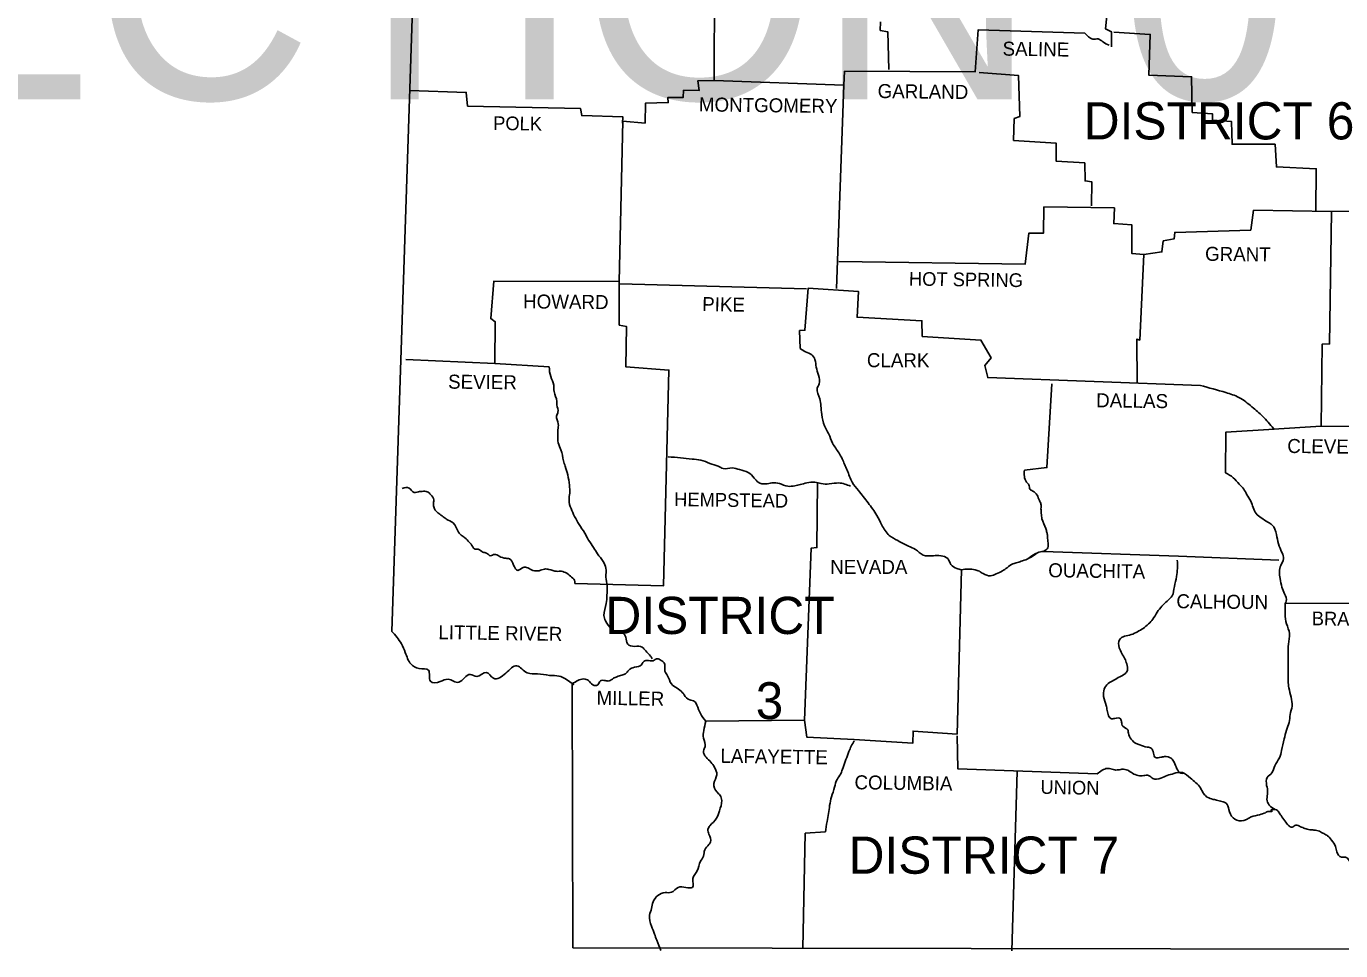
# Model space of a CAD drawing. Extents: x 166 to 3995, y -61 to 2074.
# Drawn here: x 2605.5 to 2999.8, y 1432.6 to 1709.8 of the extents above; entities that cross this region are included whole.
import ezdxf

# ---------------------------------------------------------------- set-up
doc = ezdxf.new("R2010")
doc.units = 0
for name, color, linetype in [('1', 7, 'Continuous'), ('2', 7, 'Continuous'), ('3', 7, 'Continuous')]:
    doc.layers.add(name, color=color, linetype=linetype)

msp = doc.modelspace()

# ---------------------------------------------------------------- linework, layer by layer
at = {"layer": '1'}
for points in [[(2703.71, 1956.42), (2723.96, 1793.81), (2715.15, 1528.37)], [(2812.02, 1750.86), (2811.82, 1693.62), (2806.93, 1693.52), (2807.32, 1690.59), (2802.62, 1690.68), (2802.53, 1688.53), (2797.93, 1688.53), (2798.03, 1686.97), (2791.18, 1686.77), (2791.08, 1680.8), (2784.43, 1681.39), (2783.35, 1633.25), (2745.68, 1633.35), (2744.8, 1622.19), (2746.17, 1621.22), (2746.07, 1608.69), (2719.36, 1609.87)], [(2961.91, 1722.77), (2954.86, 1723.56), (2955.16, 1720.92), (2942.34, 1720.43), (2941.95, 1716.61), (2929.91, 1715.93), (2929.23, 1709.08), (2930.99, 1708.2), (2930.99, 1703.7)], [(2922.97, 1707.81), (2890.97, 1708.78), (2890.09, 1696.16), (2850.96, 1696.36), (2850.76, 1692.15)], [(2861.72, 1711.23), (2861.62, 1708.59), (2863.87, 1708.2), (2864.26, 1696.85)], [(2931.68, 1708.1), (2942.63, 1707.41), (2942.24, 1695.18), (2955.06, 1694.69), (2955.26, 1684.03), (2961.32, 1683.54), (2961.32, 1681.68), (2967, 1681.29), (2967.19, 1674.44), (2980.11, 1674.44), (2980.5, 1667.69), (2992.44, 1667.1), (2992.34, 1654.38)], [(2891.27, 1695.97), (2903.11, 1695.09), (2903.5, 1682.76), (2901.83, 1682.17), (2901.64, 1675.62), (2914.46, 1674.74), (2914.46, 1669.35), (2922.97, 1668.86), (2923.07, 1663.48), (2925.12, 1663.19), (2925.02, 1655.95)], [(2850.76, 1692.15), (2811.82, 1693.62)], [(2850.76, 1692.15), (2848.51, 1631.2)], [(2720.54, 1690.59), (2737.46, 1690), (2737.85, 1685.89), (2771.71, 1685.2), (2772.1, 1683.05), (2784.43, 1682.66), (2784.33, 1680.8)], [(3109.06, 1665.64), (3072.08, 1666.61), (3071.88, 1654.58), (2997.03, 1654.29)], [(2849.2, 1639.32), (2905.16, 1638.53), (2906.24, 1647.83), (2910.64, 1647.83), (2910.74, 1655.66), (2931.87, 1655.36), (2931.68, 1650.67), (2937.16, 1650.27), (2937.16, 1641.66), (2940.68, 1641.37)], [(2940.68, 1641.37), (2946.16, 1642.15), (2946.55, 1645.48), (2949.78, 1646.07), (2949.97, 1648.02), (2972.77, 1648.71), (2973.65, 1654.68), (2997.03, 1654.29)], [(2997.03, 1654.09), (2996.45, 1614.56), (2994.2, 1614.47), (2993.9, 1589.91)], [(2940.68, 1641.37), (2939.5, 1615.74), (2938.62, 1616.03), (2938.72, 1602.72)], [(2783.35, 1633.25), (2783.35, 1620.24), (2785.5, 1619.85), (2785.31, 1607.71), (2798.22, 1606.74), (2796.66, 1542.06), (2770.04, 1542.75)], [(2783.55, 1632.57), (2839.51, 1631.1)], [(2837.65, 1613.19), (2837.46, 1618.57), (2839.02, 1618.67), (2840, 1631.29), (2855.07, 1630.32), (2854.68, 1622.59), (2874.15, 1621.51), (2874.24, 1616.81), (2891.85, 1615.74), (2894.89, 1610.45), (2893.03, 1608.11), (2893.91, 1604.49), (2957.7, 1602.14)], [(2746.07, 1608.69), (2762.31, 1607.71)], [(2913.09, 1602.63), (2911.62, 1577.48), (2904.87, 1576.7)], [(2993.9, 1589.91), (2979.62, 1589.03)], [(2993.9, 1589.91), (3028.54, 1589.71)], [(2979.81, 1589.03), (2965.33, 1588.15), (2965.24, 1575.92)], [(2842.84, 1572.98), (2842.64, 1553.51), (2840.88, 1553.31), (2838.92, 1501.75)], [(2910.64, 1552.34), (2951.15, 1550.87), (2981.18, 1549.69)], [(2885.98, 1546.86), (2884.71, 1497.55), (2871.5, 1498.43), (2871.41, 1494.81), (2853.79, 1495.88)], [(2983.14, 1536.68), (3027.36, 1536.78)], [(2769.26, 1512.61), (2769.46, 1433.46), (3128.04, 1432.87)], [(2853.79, 1495.88), (2839.61, 1496.67), (2838.92, 1501.75), (2809.28, 1501.46)], [(2926.69, 1485.61), (2884.91, 1487.17), (2884.71, 1497.06)], [(2902.72, 1486.29), (2901.15, 1432.58)], [(2845.18, 1468.19), (2839.12, 1467.8), (2838.43, 1433.36)]]:
    msp.add_lwpolyline(points, dxfattribs=at)
for points in [[(2930.31, 1704.19), (2928.45, 1705.16), (2926.98, 1706.04), (2925.41, 1705.95), (2924.14, 1706.73), (2922.97, 1707.81)], [(2837.65, 1613.19), (2839.22, 1612.21), (2841.08, 1611.33), (2842.05, 1609.87), (2842.45, 1607.62), (2843.13, 1605.17), (2843.33, 1602.63), (2842.74, 1601.26), (2843.52, 1598.13), (2843.82, 1595.97), (2844.11, 1593.43), (2844.89, 1590.01), (2846.16, 1587.66), (2847.34, 1584.82), (2849.29, 1581.79), (2850.96, 1578.46), (2851.74, 1576.7), (2853.21, 1573.08), (2855.07, 1570.63), (2858, 1566.91), (2860.64, 1563.1), (2862.11, 1560.26), (2864.36, 1557.13), (2866.91, 1555.57), (2870.13, 1553.9), (2872.19, 1552.92), (2874.54, 1551.26), (2877.57, 1551.06), (2879.82, 1551.06), (2881.88, 1550.18), (2882.85, 1548.42), (2884.61, 1547.25), (2885.98, 1546.86)], [(2762.31, 1607.71), (2762.8, 1604.78), (2763.68, 1602.24), (2763.78, 1600.28), (2764.66, 1597.34), (2764.66, 1596.27), (2764.96, 1594.11), (2764.56, 1592.94), (2765.05, 1590.59), (2764.96, 1588.83), (2764.96, 1587.36), (2765.05, 1584.92), (2765.84, 1582.76), (2766.62, 1579.54), (2767.11, 1577.87), (2767.89, 1575.33), (2768.38, 1572.2), (2768.48, 1569.85), (2768.28, 1567.7), (2768.87, 1565.25), (2769.95, 1562.81), (2771.32, 1560.46), (2772.98, 1557.82), (2774.15, 1555.76), (2775.62, 1553.51), (2776.79, 1551.65), (2778.56, 1549.3), (2779.34, 1547.35), (2779.34, 1544.61), (2779.73, 1542.06), (2779.63, 1539.23), (2779.44, 1536.68), (2778.75, 1533.16), (2779.24, 1531.5), (2781.1, 1529.05), (2782.27, 1528.37), (2784.33, 1527.97), (2785.31, 1526.6), (2785.89, 1524.55), (2787.95, 1523.86), (2790.2, 1523.67), (2791.27, 1522.49), (2792.74, 1520.93), (2793.23, 1520.15)], [(2957.7, 1602.14), (2965.33, 1599.98), (2969.25, 1598.52), (2973.16, 1595.68), (2976.39, 1592.84), (2979.62, 1589.22)], [(2798.03, 1580.71), (2801.74, 1580.42), (2805.17, 1580.03), (2807.81, 1579.73), (2810.55, 1578.75), (2813, 1577.87), (2814.56, 1577.19), (2817.2, 1577.38), (2819.45, 1576.89), (2822, 1576.01), (2823.86, 1574.35), (2825.03, 1573.08), (2827.28, 1572.59), (2829.14, 1572.88), (2831.39, 1572.69), (2833.93, 1571.9), (2835.99, 1572), (2837.65, 1572.39), (2839.61, 1572.88), (2842.05, 1573.08), (2843.91, 1572.69), (2846.36, 1572.59), (2849.2, 1572.88), (2852.72, 1571.9)], [(2904.87, 1576.7), (2904.87, 1574.84), (2905.55, 1573.08), (2906.24, 1572.3), (2906.53, 1571.02), (2907.41, 1570.44), (2908.68, 1569.26), (2909.37, 1567.6), (2909.86, 1566.52), (2909.86, 1565.15), (2909.96, 1563.78), (2910.15, 1562.12), (2911.33, 1559.19), (2911.62, 1558.01), (2911.81, 1557.03), (2911.91, 1555.37), (2911.91, 1553.41), (2910.64, 1552.34)], [(2965.24, 1575.92), (2967.49, 1574.45), (2969.34, 1572.49), (2970.71, 1571.02), (2971.59, 1569.36), (2972.77, 1567.4), (2974.43, 1563.69), (2975.9, 1562.41), (2977.95, 1561.14), (2979.23, 1560.26), (2980.5, 1557.42), (2981.09, 1554.59), (2982.16, 1552.04), (2982.65, 1550.09), (2981.77, 1548.13), (2981.57, 1544.22), (2982.16, 1541.57), (2982.94, 1539.62), (2983.43, 1537.37), (2983.14, 1536.68)], [(2718.19, 1571.22), (2720.34, 1571.32), (2721.81, 1570.05), (2722.69, 1570.14), (2724.25, 1570.34), (2725.72, 1570.24), (2726.8, 1569.36), (2727.68, 1567.8), (2727.58, 1566.33), (2727.68, 1565.74), (2728.36, 1564.47), (2729.54, 1563.49), (2730.81, 1562.51), (2731.98, 1561.73), (2733.94, 1560.46), (2734.14, 1560.07), (2734.92, 1558.5), (2735.9, 1557.23), (2737.07, 1556.45), (2738.34, 1555.08), (2738.93, 1554.49), (2739.91, 1553.12), (2740.98, 1553.02), (2742.45, 1552.14), (2743.53, 1551.85), (2744.7, 1551.06), (2745.88, 1551.46), (2747.34, 1550.87), (2749.3, 1550.28), (2750.38, 1550.09), (2751.65, 1548.23), (2752.92, 1546.66), (2754.49, 1547.54), (2757.42, 1546.66), (2759.28, 1546.56), (2760.94, 1547.05), (2762.22, 1546.96), (2764.56, 1546.37), (2766.03, 1546.37), (2767.6, 1545.78), (2769.06, 1544.61), (2770.04, 1543.34), (2770.04, 1542.75)], [(2908.78, 1551.95), (2906.24, 1550.28), (2904.28, 1549.5), (2902.81, 1549.01), (2901.44, 1548.62), (2899.68, 1547.44), (2898.31, 1546.47), (2896.45, 1545.59), (2894.69, 1545), (2892.54, 1545.68), (2891.37, 1546.37), (2890.09, 1546.86), (2885.98, 1546.86)], [(2906.24, 1550.28), (2908.78, 1551.95), (2910.64, 1552.34)], [(2950.75, 1549.69), (2950.56, 1544.8), (2949.87, 1541.77), (2949.19, 1539.03), (2947.72, 1537.46), (2946.16, 1535.9), (2944.69, 1534.14), (2943.42, 1531.99), (2942.14, 1530.62), (2940.48, 1529.25), (2938.82, 1528.27), (2936.96, 1527.39), (2934.9, 1526.9), (2933.44, 1525.82), (2933.34, 1523.47), (2935, 1520.15), (2935.59, 1518.58), (2935.79, 1516.72), (2935.1, 1515.65), (2933.53, 1514.77), (2931.68, 1513.69), (2930.01, 1512.71), (2928.84, 1511.05), (2928.64, 1508.8), (2929.43, 1506.16), (2929.72, 1504.59), (2930.99, 1502.14), (2931.97, 1502.24), (2933.73, 1502.14), (2933.93, 1501.65), (2934.02, 1501.17), (2934.42, 1499.89), (2935.88, 1498.82), (2936.08, 1497.84), (2936.96, 1495.98), (2938.43, 1494.71), (2939.5, 1494.32), (2941.75, 1493.63), (2942.93, 1493.34), (2944.2, 1490.5), (2945.77, 1490.6), (2946.94, 1490.79), (2948.9, 1490.31), (2949.78, 1489.13), (2950.66, 1487.17), (2951.83, 1485.8), (2952.61, 1485.8)], [(2983.14, 1536.68), (2983.53, 1530.62), (2984.41, 1527.68), (2984.12, 1524.55), (2984.02, 1521.52), (2984.02, 1518.78), (2984.02, 1516.14), (2984.02, 1513.4), (2984.22, 1511.44), (2984.9, 1508.6), (2985.19, 1505.96), (2984.61, 1503.42), (2984.31, 1501.07), (2983.53, 1498.72), (2982.85, 1496.08), (2982.06, 1492.65), (2981.38, 1490.4), (2980.01, 1488.06), (2979.13, 1485.9), (2977.76, 1484.53), (2977.56, 1482.18), (2977.86, 1480.03), (2977.66, 1478.08), (2978.35, 1476.22), (2980.11, 1474.94)], [(2715.15, 1528.37), (2717.99, 1524.65), (2719.17, 1522.01), (2720.83, 1518.58), (2723.28, 1517.21), (2726.11, 1516.72), (2726.7, 1513.4), (2729.63, 1513.3), (2731.98, 1513.98), (2735.21, 1513.1), (2738.64, 1515.45), (2740.59, 1514.86), (2743.43, 1516.04), (2745.58, 1514.28), (2749.3, 1515.84), (2752.63, 1517.99), (2755.76, 1515.94), (2758.79, 1515.65), (2762.41, 1515.16), (2765.25, 1514.96), (2767.79, 1513.69), (2769.65, 1512.42), (2769.26, 1512.61)], [(2769.26, 1512.61), (2772.68, 1514.08), (2774.15, 1513.59), (2775.42, 1512.32), (2776.89, 1512.32), (2777.67, 1513.49), (2779.14, 1513.59), (2780.32, 1513.49), (2781.59, 1514.28), (2782.66, 1514.77), (2784.13, 1515.25), (2785.21, 1515.65), (2786.19, 1516.72), (2787.95, 1517.6), (2790, 1518.29), (2790.59, 1519.27), (2791.57, 1519.66), (2793.52, 1519.56), (2794.8, 1520.15), (2795.87, 1519.66), (2796.85, 1518.97), (2797.05, 1516.43), (2797.83, 1515.06), (2799, 1512.61), (2800.67, 1511.34), (2802.23, 1510.07), (2802.82, 1509.29), (2804.48, 1507.82), (2805.95, 1507.33), (2806.64, 1506.25), (2807.71, 1503.71), (2809.28, 1501.46)], [(2809.28, 1501.46), (2808.69, 1498.62), (2808.59, 1496.37), (2809.08, 1493.73), (2808.59, 1492.46), (2809.38, 1490.6), (2810.84, 1489.13), (2811.92, 1487.57), (2812.6, 1485.32), (2811.72, 1482.77), (2812.7, 1480.13), (2813.58, 1479.15), (2814.07, 1477.59), (2813.39, 1474.55), (2812.51, 1472.3), (2810.55, 1470.05), (2809.96, 1468.98), (2810.26, 1467.51), (2810.74, 1465.16), (2810.26, 1464.48), (2808.98, 1462.81), (2808.59, 1460.95), (2807.71, 1459.39), (2806.73, 1456.55), (2805.46, 1454.2), (2805.27, 1451.56), (2803.31, 1451.56), (2801.06, 1451.56), (2799, 1450.09), (2797.15, 1450), (2794.89, 1449.11), (2793.52, 1447.26), (2793.04, 1445.2), (2792.45, 1443.24), (2793.04, 1439.92), (2793.92, 1437.57), (2794.6, 1435.71), (2795.78, 1432.68)], [(2845.18, 1468.19), (2845.67, 1471.32), (2846.16, 1473.77), (2846.46, 1476.12), (2847.04, 1478.76), (2847.92, 1481.6), (2848.71, 1483.95), (2849.78, 1485.61), (2850.47, 1487.57), (2851.35, 1489.91), (2852.23, 1492.36), (2853.79, 1495.49)], [(2926.69, 1485.61), (2928.25, 1486.69), (2929.72, 1487.27), (2931.19, 1486.98), (2932.75, 1486.78), (2934.12, 1486.98), (2935.88, 1486.69), (2937.35, 1485.8), (2939.01, 1485.12), (2940.68, 1485.12), (2942.14, 1485.12), (2943.42, 1484.24), (2945.77, 1484.34), (2947.72, 1485.12), (2949.68, 1485.71), (2952.32, 1486), (2954.67, 1484.34), (2956.33, 1482.97), (2957.7, 1481.4), (2958.68, 1479.64), (2959.76, 1478.66), (2961.52, 1477.98), (2962.89, 1477.68), (2964.55, 1477.19), (2965.43, 1476.8), (2966.21, 1474.94), (2967.49, 1472.4), (2969.93, 1471.52), (2972.96, 1472.69), (2975.41, 1473.38), (2977.17, 1473.97), (2978.25, 1474.36), (2979.23, 1474.46), (2978.93, 1474.65), (2980.11, 1474.94), (2981.18, 1474.16), (2981.87, 1473.09), (2983.04, 1471.52), (2984.12, 1470.15), (2985.19, 1469.66), (2986.27, 1470.25), (2987.74, 1469.76), (2989.01, 1469.27), (2990.48, 1468.88), (2991.75, 1468.78), (2993.41, 1468.39), (2994.69, 1467.7), (2995.86, 1467.02), (2997.03, 1465.75), (2998.21, 1463.79), (2998.6, 1462.23), (2999.97, 1460.66), (3001.24, 1460.66), (3003.1, 1458.12), (3003.78, 1457.14), (3005.25, 1455.38), (3006.33, 1455.38), (3008.38, 1454.98)]]:
    msp.add_spline(points, degree=3, dxfattribs=at)

# ---------------------------------------------------------------- texts
at = {"layer": '2'}
for s, height, p in [('ROUTE 135 SECTION 2 & ROUTE 139 SECTION 0', 68, (872.06, 1687.93)), ('CLARK', 4.207, (2857.63, 1607.59)), ('NEVADA', 4.207, (2846.65, 1545.59))]:
    msp.add_text(s, height=height, dxfattribs=at).set_placement(p)
for s, height, rotation, p in [('SALINE', 4.207, 359.1491, (2898.31, 1701.05)), ('GARLAND', 4.207, 359.3658, (2860.84, 1688.33)), ('MONTGOMERY', 4.207, 359.2944, (2807.22, 1684.32)), ('POLK', 4.108, 359.2152, (2745.49, 1678.75)), ('GRANT', 4.207, 359.4032, (2959.07, 1639.51)), ('HOT SPRING', 4.109, 359.2216, (2870.23, 1632.08)), ('HOWARD', 4.207, 359.5145, (2754.49, 1625.23)), ('PIKE', 4.206, 359.0452, (2808.2, 1624.44)), ('SEVIER', 4.207, 359.4271, (2731.98, 1601.16)), ('DALLAS', 4.206, 359.2462, (2926.39, 1595.58)), ('CLEVELAND', 4.207, 359.3377, (2983.73, 1581.88)), ('HEMPSTEAD', 4.108, 359.1885, (2799.79, 1565.94)), ('OUACHITA', 4.207, 359.2043, (2912.01, 1544.61)), ('CALHOUN', 4.207, 359.3634, (2950.46, 1535.31)), ('BRADLEY', 4.108, 359.1449, (2991.07, 1530.22)), ('LITTLE RIVER', 4.2073, 359.1697, (2729.05, 1526.02)), ('MILLER', 4.206, 359.1319, (2776.5, 1506.35)), ('LAFAYETTE', 4.206, 359.1839, (2813.68, 1488.94)), ('COLUMBIA', 4.206, 359.2125, (2853.89, 1481.01)), ('UNION', 4.109, 358.9584, (2909.66, 1479.64))]:
    msp.add_text(s, height=height, rotation=rotation, dxfattribs=at).set_placement(p)
at = {"layer": '3'}
for s, height, p in [('DISTRICT 6', 11.154, (2922.67, 1675.91)), ('DISTRICT', 11.154, (2779.19, 1527.57)), ('3', 11.06, (2824.3, 1502.04)), ('DISTRICT 7', 11.154, (2852.13, 1455.67))]:
    msp.add_text(s, height=height, dxfattribs=at).set_placement(p)

doc.saveas('drawing.dxf')
